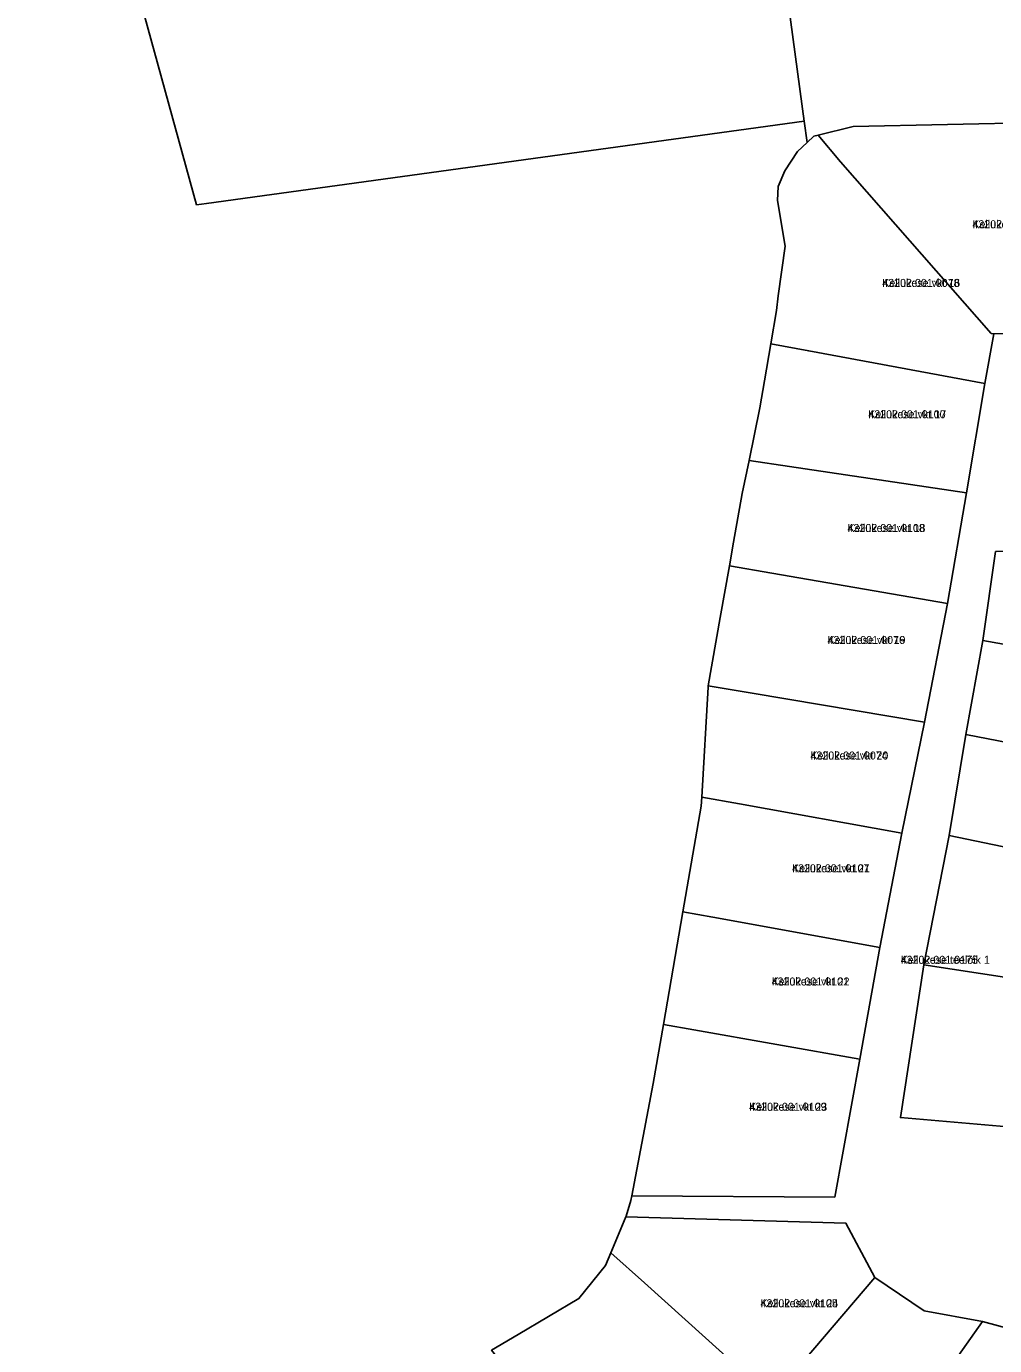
# Model space of a CAD drawing. Extents: x 661852 to 683758, y 6469495 to 6482657.
# Drawn here: x 665538.5 to 665720.1, y 6471512.2 to 6471759.5 of the extents above; entities that cross this region are included whole.
import ezdxf

# ---------------------------------------------------------------- set-up
doc = ezdxf.new("R2010")
doc.units = 0
for name, color, linetype in [('L_AADRESS', 7, 'Continuous'), ('PIIR', 7, 'Continuous'), ('TUNNUS', 7, 'Continuous')]:
    doc.layers.add(name, color=color, linetype=linetype)

msp = doc.modelspace()

# ---------------------------------------------------------------- linework, layer by layer
at = {"layer": 'PIIR'}
for points in [[(665658.68, 6471833.99), (665672.39, 6471830.94), (665684.4, 6471741.78), (665572.32, 6471726.35), (665570.44, 6471726.09), (665554.64, 6471783.35), (665554.24, 6471786.09), (665538.52, 6471807.89), (665548.78, 6471814.34), (665576.51, 6471828.03), (665596.59, 6471832.94), (665593.99, 6471846.25), (665589.88, 6471856.16), (665580.91, 6471875.15), (665585.91, 6471876.12), (665594.36, 6471858.44), (665598.71, 6471847.76), (665601.62, 6471833.95), (665629.32, 6471837.32)], [(665719.91, 6471701.87), (665719.44, 6471701.97), (665691.18, 6471734.14), (665686.99, 6471739.11), (665693.53, 6471740.75), (665728.91, 6471741.5), (665729.19, 6471734.62), (665730.5, 6471701.93)], [(665719.91, 6471701.87), (665718.22, 6471692.57), (665685.23, 6471698.71), (665678.11, 6471700.04), (665679.18, 6471706.3), (665679.47, 6471709), (665680.83, 6471718.35), (665679.38, 6471726.86), (665679.47, 6471729.5), (665680.74, 6471732.48), (665683.12, 6471736.06), (665684.92, 6471737.76), (665686.19, 6471738.96), (665686.99, 6471739.11), (665691.18, 6471734.14), (665719.44, 6471701.97)], [(665714.78, 6471672.11), (665681.62, 6471677.01), (665674.03, 6471678.14), (665676.06, 6471688.02), (665676.92, 6471693.08), (665678.11, 6471700.04), (665685.23, 6471698.71), (665718.22, 6471692.57)], [(665711.22, 6471651.35), (665678.3, 6471657.04), (665670.36, 6471658.41), (665671.15, 6471662.86), (665672.76, 6471671.95), (665674.03, 6471678.14), (665681.62, 6471677.01), (665714.78, 6471672.11)], [(665720.26, 6471661.11), (665741.56, 6471661.43), (665749.56, 6471661.56), (665750.25, 6471638.66), (665717.85, 6471644.43)], [(665706.95, 6471629.1), (665674.63, 6471634.55), (665666.39, 6471635.94), (665668.64, 6471648.72), (665670.36, 6471658.41), (665678.3, 6471657.04), (665711.22, 6471651.35)], [(665717.85, 6471644.43), (665750.25, 6471638.66), (665749.89, 6471619.98), (665714.66, 6471626.82)], [(665706.95, 6471629.1), (665702.67, 6471608.28), (665672.26, 6471613.77), (665665.17, 6471615.05), (665666.35, 6471635.68), (665666.39, 6471635.94), (665674.63, 6471634.55)], [(665714.66, 6471626.82), (665749.89, 6471619.98), (665751.55, 6471599.84), (665738.07, 6471602.37), (665711.59, 6471607.86)], [(665698.59, 6471586.89), (665667.25, 6471592.55), (665661.63, 6471593.56), (665665.07, 6471613.38), (665665.17, 6471615.05), (665672.26, 6471613.77), (665702.67, 6471608.28)], [(665711.59, 6471607.86), (665738.07, 6471602.37), (665734.21, 6471579.45), (665706.84, 6471583.61)], [(665694.8, 6471565.94), (665663.67, 6471571.44), (665657.97, 6471572.45), (665661.63, 6471593.56), (665667.25, 6471592.55), (665698.59, 6471586.89)], [(665706.84, 6471583.61), (665734.21, 6471579.45), (665741.58, 6471562.02), (665731.2, 6471552.53), (665702.43, 6471554.99)], [(665694.8, 6471565.94), (665690.12, 6471540.09), (665652.04, 6471540.32), (665656.06, 6471561.4), (665657.97, 6471572.45), (665663.67, 6471571.44)], [(665650.95, 6471536.39), (665692.2, 6471535.2), (665697.63, 6471524.99), (665678.39, 6471502.49), (665676.71, 6471503.99), (665654.4, 6471524), (665648.12, 6471529.63)], [(665649.26, 6471484.59), (665628.33, 6471508.17), (665625.77, 6471511.37), (665630.74, 6471514.31), (665642.13, 6471521.05), (665647.12, 6471527.24), (665648.12, 6471529.63), (665654.4, 6471524), (665676.71, 6471503.99), (665651.77, 6471481.85)], [(665706.87, 6471518.76), (665717.83, 6471516.78), (665696.35, 6471486.42), (665678.39, 6471502.49), (665697.63, 6471524.99)], [(665726.1, 6471514.53), (665725.28, 6471473.59), (665701.12, 6471486.1), (665696.35, 6471486.42), (665717.83, 6471516.78)]]:
    msp.add_lwpolyline(points, close=True, dxfattribs=at)
for points in [[(665812.89, 6471779.74), (665814.19, 6471749.05), (665814.38, 6471744.07), (665808.72, 6471744.08), (665788.69, 6471742.75), (665768.63, 6471742.33), (665748.66, 6471741.91), (665728.91, 6471741.5), (665693.53, 6471740.75), (665686.99, 6471739.11), (665686.19, 6471738.96), (665684.92, 6471737.76), (665684.4, 6471741.78), (665672.39, 6471830.94)], [(665554.64, 6471783.35), (665570.44, 6471726.09), (665572.32, 6471726.35), (665684.4, 6471741.78), (665684.92, 6471737.76), (665683.12, 6471736.06), (665680.74, 6471732.48), (665679.47, 6471729.5), (665679.38, 6471726.86), (665680.83, 6471718.35), (665679.47, 6471709), (665679.18, 6471706.3), (665678.11, 6471700.04), (665676.92, 6471693.08), (665676.06, 6471688.02), (665674.03, 6471678.14), (665672.76, 6471671.95), (665671.15, 6471662.86), (665670.36, 6471658.41), (665668.64, 6471648.72), (665666.39, 6471635.94), (665666.35, 6471635.68), (665665.17, 6471615.05), (665665.07, 6471613.38), (665661.63, 6471593.56), (665657.97, 6471572.45), (665656.06, 6471561.4), (665652.04, 6471540.32), (665651.88, 6471539.45), (665651.01, 6471536.53), (665650.95, 6471536.39), (665648.12, 6471529.63), (665647.12, 6471527.24), (665642.13, 6471521.05), (665630.74, 6471514.31), (665625.77, 6471511.37)], [(665726.1, 6471514.53), (665717.83, 6471516.78), (665706.87, 6471518.76), (665697.63, 6471524.99), (665692.2, 6471535.2), (665650.95, 6471536.39), (665651.01, 6471536.53), (665651.88, 6471539.45), (665652.04, 6471540.32), (665690.12, 6471540.09), (665694.8, 6471565.94), (665698.59, 6471586.89), (665702.67, 6471608.28), (665706.95, 6471629.1), (665711.22, 6471651.35), (665714.78, 6471672.11), (665718.22, 6471692.57), (665719.91, 6471701.87), (665730.5, 6471701.93)], [(665720.26, 6471661.11), (665717.86, 6471644.43), (665714.67, 6471626.82), (665711.59, 6471607.86), (665706.84, 6471583.61), (665702.43, 6471554.99), (665731.2, 6471552.53)]]:
    msp.add_lwpolyline(points, dxfattribs=at)

# ---------------------------------------------------------------- texts
at = {"layer": 'L_AADRESS'}
for s, p in [('Kellukese vkt 15', (665715.91, 6471721.69)), ('Kellukese vkt 16', (665699.01, 6471710.69)), ('Kellukese vkt 17', (665696.39, 6471686.07)), ('Kellukese vkt 18', (665692.5, 6471664.75)), ('Kellukese vkt 19', (665688.76, 6471643.76)), ('Kellukese vkt 20', (665685.54, 6471622.11)), ('Kellukese vkt 21', (665682.1, 6471600.97)), ('Kellukese teelõik 1', (665702.46, 6471583.82)), ('Kellukese vkt 22', (665678.27, 6471579.75)), ('Kellukese vkt 23', (665674.07, 6471556.27)), ('Kellukese vkt 24', (665676.18, 6471519.44))]:
    msp.add_text(s, height=1.5, dxfattribs=at).set_placement(p)
at = {"layer": 'TUNNUS'}
for s, p in [('43202:001:0080', (665715.91, 6471721.69)), ('43202:001:0078', (665699.01, 6471710.69)), ('43202:001:0100', (665696.39, 6471686.07)), ('43202:001:0108', (665692.5, 6471664.75)), ('43202:001:0076', (665688.76, 6471643.76)), ('43202:001:0074', (665685.54, 6471622.11)), ('43202:001:0107', (665682.1, 6471600.97)), ('43202:001:0175', (665702.46, 6471583.82)), ('43202:001:0101', (665678.27, 6471579.75)), ('43202:001:0109', (665674.07, 6471556.27)), ('43202:001:0105', (665676.18, 6471519.44))]:
    msp.add_text(s, height=1.5, dxfattribs=at).set_placement(p)

doc.saveas('drawing.dxf')
